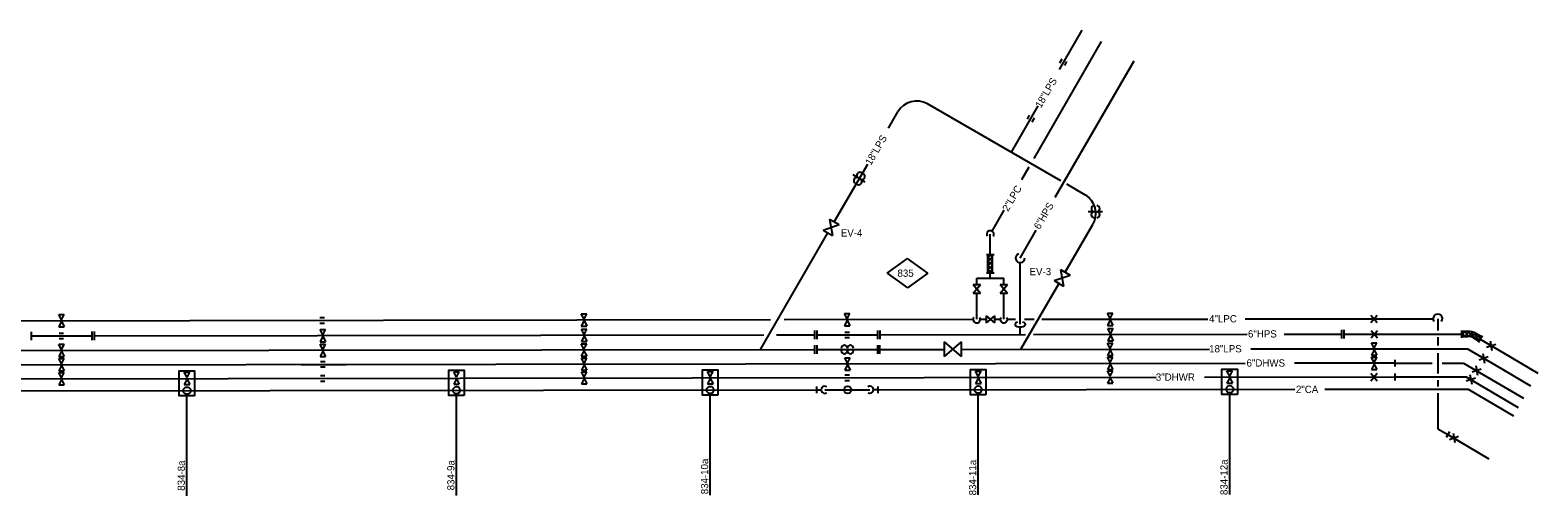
# Model space of a CAD drawing. Extents: x 9888 to 10178, y 10284 to 10314.
# Drawn here: x 10109 to 10178.2, y 10284.2 to 10305.6 of the extents above; entities that cross this region are included whole.
import ezdxf

# ---------------------------------------------------------------- set-up
doc = ezdxf.new("R2010")
doc.units = 0
for name, color, linetype in [('Level 51', 7, 'Continuous'), ('Level 52', 7, 'Continuous'), ('Level 53', 7, 'Continuous'), ('Level 54', 7, 'Continuous'), ('Level 55', 7, 'Continuous'), ('M-EQPM-N', 7, 'Continuous'), ('M-STEM-CONP', 7, 'Continuous'), ('M-STEM-CONP-N', 7, 'Continuous'), ('P-CMPA-PIPE', 7, 'Continuous'), ('P-CMPA-PIPE-N', 7, 'Continuous'), ('P-DOMW-HPIP', 7, 'Continuous'), ('P-DOMW-HPIP-N', 7, 'Continuous')]:
    doc.layers.add(name, color=color, linetype=linetype)

msp = doc.modelspace()

# ---------------------------------------------------------------- linework, layer by layer
at = {"layer": 'Level 51'}
for p, q in [((10155.104, 10299.749), (10158.206, 10305.122)), ((10154.54, 10298.773), (10154.881, 10299.363)), ((10153.174, 10296.406), (10153.727, 10297.365)), ((10153.092, 10295.333), (10153.092, 10296.264)), ((10148.356, 10294.475), (10149.289, 10295.148)), ((10150.222, 10294.475), (10149.289, 10295.148)), ((10152.92, 10295.333), (10153.263, 10295.333)), ((10152.994, 10295.213), (10152.968, 10295.239)), ((10152.968, 10295.188), (10152.994, 10295.213)), ((10152.994, 10295.025), (10152.968, 10295.051)), ((10152.968, 10294.999), (10152.994, 10295.025)), ((10152.994, 10295.213), (10153.091, 10295.311)), ((10152.994, 10295.025), (10153.195, 10295.227)), ((10153.195, 10295.012), (10152.994, 10295.213)), ((10152.994, 10295.025), (10153.088, 10294.931)), ((10153.088, 10294.931), (10152.994, 10294.836)), ((10153.195, 10295.2), (10153.085, 10295.311)), ((10153.088, 10294.931), (10153.195, 10295.038)), ((10153.195, 10294.823), (10153.088, 10294.931)), ((10148.356, 10294.475), (10149.289, 10293.803)), ((10150.222, 10294.475), (10149.289, 10293.803)), ((10152.469, 10293.952), (10152.469, 10294.248)), ((10152.469, 10294.248), (10153.714, 10294.248)), ((10152.92, 10294.499), (10153.263, 10294.499)), ((10152.994, 10294.836), (10152.968, 10294.862)), ((10152.968, 10294.811), (10152.994, 10294.836)), ((10152.994, 10294.648), (10152.968, 10294.674)), ((10152.968, 10294.622), (10152.994, 10294.648)), ((10152.994, 10294.648), (10153.195, 10294.85)), ((10153.195, 10294.634), (10152.994, 10294.836)), ((10153.124, 10294.518), (10152.994, 10294.648)), ((10153.052, 10294.518), (10153.195, 10294.661)), ((10153.092, 10294.248), (10153.092, 10294.499)), ((10153.714, 10293.952), (10153.714, 10294.248)), ((10152.302, 10293.952), (10152.636, 10293.952)), ((10152.302, 10293.564), (10152.636, 10293.952)), ((10152.302, 10293.952), (10152.636, 10293.564)), ((10152.302, 10293.564), (10152.636, 10293.564)), ((10152.469, 10292.355), (10152.469, 10293.564)), ((10153.547, 10293.952), (10153.881, 10293.952)), ((10153.547, 10293.564), (10153.881, 10293.952)), ((10153.547, 10293.952), (10153.881, 10293.564)), ((10153.547, 10293.564), (10153.881, 10293.564)), ((10153.714, 10292.355), (10153.714, 10293.564)), ((10073.354, 10292.244), (10142.991, 10292.341)), ((10110.434, 10292.333), (10110.31, 10292.581)), ((10110.31, 10292.581), (10110.558, 10292.581)), ((10110.434, 10292.264), (10110.31, 10292.016)), ((10110.434, 10292.333), (10110.558, 10292.581)), ((10110.434, 10292.264), (10110.558, 10292.016)), ((10122.307, 10292.436), (10122.511, 10292.436)), ((10122.307, 10292.186), (10122.511, 10292.186)), ((10134.434, 10292.365), (10134.31, 10292.612)), ((10134.31, 10292.612), (10134.558, 10292.612)), ((10134.434, 10292.295), (10134.31, 10292.047)), ((10134.434, 10292.365), (10134.558, 10292.612)), ((10134.434, 10292.295), (10134.558, 10292.047)), ((10143.628, 10292.342), (10152.304, 10292.355)), ((10146.518, 10292.38), (10146.394, 10292.628)), ((10146.394, 10292.628), (10146.641, 10292.628)), ((10146.518, 10292.311), (10146.394, 10292.063)), ((10146.518, 10292.38), (10146.641, 10292.628)), ((10146.518, 10292.311), (10146.641, 10292.063)), ((10152.633, 10292.356), (10152.883, 10292.356)), ((10152.913, 10292.189), (10152.913, 10292.523)), ((10153.301, 10292.189), (10152.913, 10292.523)), ((10152.913, 10292.189), (10153.301, 10292.523)), ((10153.301, 10292.189), (10153.301, 10292.523)), ((10153.301, 10292.356), (10153.55, 10292.356)), ((10153.879, 10292.357), (10154.246, 10292.357)), ((10154.658, 10292.357), (10155.112, 10292.358)), ((10155.461, 10292.359), (10163.09, 10292.368)), ((10158.601, 10292.396), (10158.477, 10292.644)), ((10158.477, 10292.644), (10158.725, 10292.644)), ((10158.601, 10292.326), (10158.477, 10292.079)), ((10158.601, 10292.396), (10158.725, 10292.644)), ((10158.601, 10292.326), (10158.725, 10292.079)), ((10164.799, 10292.371), (10173.411, 10292.382)), ((10170.572, 10292.212), (10170.864, 10292.552)), ((10170.572, 10292.552), (10170.864, 10292.212)), ((10173.644, 10292.382), (10173.644, 10291.845)), ((10110.31, 10292.016), (10110.558, 10292.016)), ((10134.31, 10292.047), (10134.558, 10292.047)), ((10134.441, 10291.66), (10134.317, 10291.907)), ((10134.317, 10291.907), (10134.565, 10291.907)), ((10134.441, 10291.59), (10134.317, 10291.342)), ((10134.441, 10291.66), (10134.565, 10291.907)), ((10134.441, 10291.59), (10134.565, 10291.342)), ((10143.272, 10291.637), (10145.018, 10291.64)), ((10145.025, 10291.835), (10145.025, 10291.444)), ((10145.128, 10291.835), (10145.128, 10291.444)), ((10145.128, 10291.64), (10147.924, 10291.644)), ((10146.394, 10292.063), (10146.641, 10292.063)), ((10146.416, 10291.768), (10146.62, 10291.768)), ((10146.416, 10291.518), (10146.62, 10291.518)), ((10147.924, 10291.448), (10147.924, 10291.839)), ((10148.027, 10291.448), (10148.027, 10291.839)), ((10154.466, 10291.652), (10154.466, 10292.007)), ((10158.477, 10292.079), (10158.725, 10292.079)), ((10158.608, 10291.691), (10158.484, 10291.939)), ((10158.484, 10291.939), (10158.732, 10291.939)), ((10158.608, 10291.622), (10158.484, 10291.374)), ((10158.608, 10291.691), (10158.732, 10291.939)), ((10158.608, 10291.622), (10158.732, 10291.374)), ((10166.585, 10291.668), (10169.227, 10291.671)), ((10169.227, 10291.866), (10169.227, 10291.475)), ((10169.33, 10291.866), (10169.33, 10291.475)), ((10169.33, 10291.671), (10172.125, 10291.674)), ((10169.553, 10291.671), (10174.73, 10291.676)), ((10170.585, 10291.502), (10170.877, 10291.842)), ((10170.585, 10291.842), (10170.877, 10291.502)), ((10173.644, 10291.539), (10173.644, 10291.151)), ((10174.754, 10291.645), (10174.884, 10291.775)), ((10174.754, 10291.716), (10174.897, 10291.573)), ((10174.858, 10291.801), (10174.884, 10291.775)), ((10174.871, 10291.573), (10175.072, 10291.775)), ((10174.884, 10291.775), (10174.91, 10291.801)), ((10174.884, 10291.775), (10175.086, 10291.573)), ((10175.047, 10291.801), (10175.193, 10291.547)), ((10175.059, 10291.573), (10175.248, 10291.762)), ((10175.072, 10291.775), (10175.098, 10291.801)), ((10175.407, 10291.693), (10175.166, 10291.555)), ((10175.209, 10291.779), (10175.282, 10291.503)), ((10175.259, 10291.516), (10175.535, 10291.589)), ((10175.363, 10291.719), (10175.372, 10291.684)), ((10175.372, 10291.684), (10175.445, 10291.408)), ((10175.526, 10291.625), (10175.535, 10291.589)), ((10175.535, 10291.589), (10175.57, 10291.599)), ((10175.535, 10291.589), (10175.57, 10291.456)), ((10134.317, 10291.342), (10134.565, 10291.342)), ((10158.484, 10291.374), (10158.732, 10291.374)), ((10173.644, 10290.804), (10173.644, 10289.865)), ((10175.422, 10291.421), (10175.573, 10291.462)), ((10173.644, 10289.558), (10173.644, 10289.273)), ((10173.644, 10288.966), (10173.644, 10287.329)), ((10173.644, 10287.329), (10174.11, 10287.056)), ((10174.189, 10287.191), (10174.03, 10286.921))]:
    msp.add_line(p, q, dxfattribs=at)
msp.add_lwpolyline([(10153.195, 10295.311), (10152.968, 10295.311), (10152.968, 10294.518), (10153.195, 10294.518)], close=True, dxfattribs=at)
for centre, radius, start, end in [((10153.092, 10296.264), 0.164, 326.0383, 213.83623), ((10152.469, 10292.355), 0.164, 146.0383, 33.83623), ((10153.714, 10292.355), 0.164, 146.0383, 33.83623), ((10173.644, 10292.382), 0.214, 326.0383, 213.83623)]:
    msp.add_arc(centre, radius, start, end, dxfattribs=at)
at = {"layer": 'Level 52'}
for p, q in [((10174.11, 10287.056), (10175.992, 10285.951)), ((10174.175, 10286.836), (10174.599, 10286.98)), ((10174.347, 10287.128), (10174.426, 10286.688))]:
    msp.add_line(p, q, dxfattribs=at)
at = {"layer": 'Level 53'}
for p, q in [((10175.592, 10291.443), (10176.66, 10290.816)), ((10175.881, 10291.076), (10176.305, 10291.221)), ((10176.054, 10291.369), (10176.132, 10290.928)), ((10176.66, 10290.816), (10178.239, 10289.888))]:
    msp.add_line(p, q, dxfattribs=at)
at = {"layer": 'Level 54'}
for p, q in [((10174.735, 10291.849), (10174.735, 10291.505)), ((10174.754, 10291.801), (10174.754, 10291.573)), ((10175.02, 10291.801), (10174.754, 10291.801)), ((10174.754, 10291.573), (10175.026, 10291.573)), ((10175.243, 10291.65), (10175.241, 10291.658)), ((10175.277, 10291.505), (10175.518, 10291.366)), ((10175.632, 10291.563), (10175.397, 10291.699)), ((10175.675, 10291.594), (10175.502, 10291.296)), ((10175.518, 10291.366), (10175.632, 10291.563))]:
    msp.add_line(p, q, dxfattribs=at)
for centre, radius, start in [((10175.02, 10291.051), 0.75, 59.85951), ((10175.026, 10291.073), 0.5, 59.8589)]:
    msp.add_arc(centre, radius, start, 90, dxfattribs=at)
at = {"layer": 'Level 55'}
for p, q in [((10171.669, 10289.707), (10174.94, 10289.711)), ((10174.94, 10289.711), (10177.33, 10288.307)), ((10174.95, 10289.523), (10175.374, 10289.668)), ((10175.123, 10289.816), (10175.201, 10289.375))]:
    msp.add_line(p, q, dxfattribs=at)
at = {"layer": 'M-EQPM-N'}
for p, q in [((10116.199, 10284.243), (10116.199, 10288.84)), ((10128.58, 10284.26), (10128.58, 10288.857)), ((10140.233, 10284.275), (10140.233, 10288.872)), ((10152.541, 10284.291), (10152.541, 10288.889)), ((10164.086, 10284.307), (10164.086, 10288.904))]:
    msp.add_line(p, q, dxfattribs=at)
for points in [[(10116.552, 10288.84), (10115.847, 10288.84), (10115.847, 10289.995), (10116.552, 10289.995)], [(10128.933, 10288.857), (10128.228, 10288.857), (10128.228, 10290.012), (10128.933, 10290.012)], [(10140.586, 10288.872), (10139.881, 10288.872), (10139.881, 10290.027), (10140.586, 10290.027)], [(10152.893, 10288.889), (10152.188, 10288.889), (10152.188, 10290.043), (10152.893, 10290.043)], [(10164.438, 10288.904), (10163.733, 10288.904), (10163.733, 10290.059), (10164.438, 10290.059)]]:
    msp.add_lwpolyline(points, close=True, dxfattribs=at)
at = {"layer": 'M-STEM-CONP'}
for p, q in [((10156.264, 10303.841), (10157.305, 10305.644)), ((10156.077, 10297.962), (10159.702, 10304.24)), ((10156.292, 10304.148), (10156.394, 10304.325)), ((10156.509, 10304.023), (10156.611, 10304.2)), ((10148.415, 10301.14), (10148.846, 10301.887)), ((10156.332, 10298.72), (10150.213, 10302.253)), ((10154.064, 10300.03), (10155.293, 10302.159)), ((10154.797, 10301.556), (10154.9, 10301.733)), ((10155.014, 10301.431), (10155.116, 10301.608)), ((10145.929, 10296.835), (10147.462, 10299.489)), ((10146.995, 10298.871), (10146.789, 10298.99)), ((10147.124, 10298.797), (10147.124, 10298.797)), ((10147.353, 10298.664), (10147.152, 10298.78)), ((10157.44, 10298.08), (10156.608, 10298.561)), ((10157.83, 10297.299), (10157.592, 10297.299)), ((10157.979, 10297.3), (10157.978, 10297.3)), ((10158.243, 10297.299), (10158.011, 10297.299)), ((10142.536, 10290.962), (10145.636, 10296.331)), ((10145.42, 10296.457), (10146.146, 10296.709)), ((10145.42, 10296.457), (10145.852, 10296.205)), ((10145.713, 10296.961), (10146.146, 10296.709)), ((10145.713, 10296.961), (10145.852, 10296.205)), ((10154.466, 10295.171), (10155.205, 10296.451)), ((10156.537, 10294.516), (10157.806, 10296.714)), ((10154.466, 10292.127), (10154.466, 10294.957)), ((10156.029, 10294.137), (10156.755, 10294.388)), ((10156.323, 10294.641), (10156.755, 10294.388)), ((10156.323, 10294.641), (10156.462, 10293.885)), ((10154.495, 10290.978), (10156.234, 10293.99)), ((10156.029, 10294.137), (10156.462, 10293.885)), ((10109.049, 10291.788), (10109.049, 10291.397)), ((10109.049, 10291.592), (10111.844, 10291.596)), ((10110.332, 10291.721), (10110.536, 10291.721)), ((10110.332, 10291.471), (10110.536, 10291.471)), ((10111.844, 10291.4), (10111.844, 10291.791)), ((10111.948, 10291.4), (10111.948, 10291.791)), ((10111.948, 10291.596), (10142.691, 10291.637)), ((10122.441, 10291.644), (10122.317, 10291.892)), ((10122.317, 10291.892), (10122.565, 10291.892)), ((10122.441, 10291.575), (10122.317, 10291.327)), ((10122.441, 10291.644), (10122.565, 10291.892)), ((10122.441, 10291.575), (10122.565, 10291.327)), ((10148.027, 10291.644), (10154.711, 10291.653)), ((10155.07, 10291.653), (10164.895, 10291.666)), ((10085.43, 10290.887), (10145.023, 10290.966)), ((10110.432, 10290.961), (10110.309, 10291.209)), ((10110.309, 10291.209), (10110.556, 10291.209)), ((10110.432, 10290.892), (10110.309, 10290.644)), ((10110.432, 10290.961), (10110.556, 10291.209)), ((10110.432, 10290.892), (10110.556, 10290.644)), ((10122.432, 10290.961), (10122.309, 10291.209)), ((10122.309, 10291.209), (10122.556, 10291.209)), ((10122.432, 10290.892), (10122.309, 10290.644)), ((10122.317, 10291.327), (10122.565, 10291.327)), ((10122.432, 10290.961), (10122.556, 10291.209)), ((10122.432, 10290.892), (10122.556, 10290.644)), ((10148.03, 10290.97), (10150.976, 10290.974)), ((10151.753, 10290.975), (10163.153, 10290.99)), ((10165.058, 10290.992), (10175.014, 10291.003)), ((10170.724, 10291.024), (10170.6, 10291.272)), ((10170.6, 10291.272), (10170.848, 10291.272)), ((10170.724, 10290.954), (10170.6, 10290.707)), ((10170.724, 10291.024), (10170.848, 10291.272)), ((10170.724, 10290.954), (10170.848, 10290.707)), ((10175.014, 10291.003), (10176.319, 10290.236)), ((10175.712, 10290.789), (10175.79, 10290.348)), ((10110.309, 10290.644), (10110.556, 10290.644)), ((10122.309, 10290.644), (10122.556, 10290.644)), ((10170.6, 10290.707), (10170.848, 10290.707)), ((10175.539, 10290.496), (10175.963, 10290.64)), ((10176.319, 10290.236), (10177.903, 10289.306))]:
    msp.add_line(p, q, dxfattribs=at)
for centre, radius, start, end in [((10149.712, 10301.387), 1, 59.99985, 149.99956), ((10147.102, 10298.971), 0.14, 60, 240), ((10146.962, 10298.729), 0.14, 60, 240), ((10147.054, 10298.676), 0.14, 240, 60), ((10147.194, 10298.918), 0.14, 240, 60), ((10156.94, 10297.214), 1, 329.99958, 59.99986), ((10157.872, 10297.16), 0.14, 90, 270), ((10157.873, 10297.44), 0.14, 90, 270), ((10157.978, 10297.44), 0.14, 270, 90), ((10157.979, 10297.16), 0.14, 270, 90), ((10154.466, 10295.171), 0.214, 113.08412, 0.88206)]:
    msp.add_arc(centre, radius, start, end, dxfattribs=at)
msp.add_ellipse((10154.466, 10292.127), major_axis=(-0.239, 0), ratio=0.503291, start_param=5.263815, end_param=10.432096, dxfattribs=at)
at = {"layer": 'M-STEM-CONP-N'}
for p, q in [((10134.432, 10290.977), (10134.309, 10291.225)), ((10134.309, 10291.225), (10134.556, 10291.225)), ((10134.432, 10290.907), (10134.309, 10290.66)), ((10134.432, 10290.977), (10134.556, 10291.225)), ((10134.432, 10290.907), (10134.556, 10290.66)), ((10145.023, 10291.161), (10145.023, 10290.77)), ((10145.127, 10291.161), (10145.127, 10290.77)), ((10145.127, 10290.966), (10147.922, 10290.97)), ((10147.922, 10290.774), (10147.922, 10291.165)), ((10148.025, 10290.774), (10148.025, 10291.165)), ((10150.976, 10291.316), (10150.976, 10290.648)), ((10150.976, 10291.316), (10151.753, 10290.648)), ((10151.753, 10291.316), (10150.976, 10290.648)), ((10151.753, 10291.316), (10151.753, 10290.648)), ((10158.599, 10291.008), (10158.475, 10291.256)), ((10158.475, 10291.256), (10158.723, 10291.256)), ((10158.599, 10290.939), (10158.475, 10290.691)), ((10158.599, 10291.008), (10158.723, 10291.256)), ((10158.599, 10290.939), (10158.723, 10290.691)), ((10134.309, 10290.66), (10134.556, 10290.66)), ((10158.475, 10290.691), (10158.723, 10290.691))]:
    msp.add_line(p, q, dxfattribs=at)
for centre, start, end in [((10146.39, 10291.022), 0, 180), ((10146.39, 10290.917), 180, 0), ((10146.67, 10291.023), 0, 180), ((10146.67, 10290.916), 180, 0)]:
    msp.add_arc(centre, 0.14, start, end, dxfattribs=at)
at = {"layer": 'P-CMPA-PIPE'}
for p, q in [((10085.43, 10289.037), (10145.135, 10289.116)), ((10147.925, 10289.12), (10167.072, 10289.145)), ((10168.456, 10289.146), (10175.033, 10289.153)), ((10175.033, 10289.153), (10177.119, 10287.928))]:
    msp.add_line(p, q, dxfattribs=at)
at = {"layer": 'P-CMPA-PIPE-N'}
for p, q in [((10145.127, 10288.959), (10145.127, 10289.273)), ((10145.127, 10289.116), (10145.322, 10289.116)), ((10145.487, 10289.116), (10147.561, 10289.119)), ((10147.922, 10289.12), (10147.726, 10289.119)), ((10147.922, 10289.276), (10147.922, 10288.963))]:
    msp.add_line(p, q, dxfattribs=at)
for centre in [(10116.2, 10289.078), (10128.581, 10289.094), (10140.234, 10289.109), (10146.544, 10289.114), (10152.542, 10289.126), (10164.087, 10289.141)]:
    msp.add_circle(centre, 0.167, dxfattribs=at)
for centre, start, end in [((10145.487, 10289.116), 56.0383, 303.83623), ((10147.561, 10289.119), 236.0383, 123.83623)]:
    msp.add_arc(centre, 0.164, start, end, dxfattribs=at)
at = {"layer": 'P-DOMW-HPIP'}
for p, q in [((10171.669, 10290.344), (10173.391, 10290.346)), ((10173.838, 10290.346), (10174.831, 10290.347)), ((10174.831, 10290.347), (10177.58, 10288.733)), ((10175.217, 10289.937), (10175.641, 10290.082)), ((10175.39, 10290.23), (10175.468, 10289.789))]:
    msp.add_line(p, q, dxfattribs=at)
at = {"layer": 'P-DOMW-HPIP-N'}
for p, q in [((10075.709, 10290.221), (10164.791, 10290.337)), ((10110.434, 10290.305), (10110.31, 10290.553)), ((10110.31, 10290.553), (10110.558, 10290.553)), ((10110.434, 10290.236), (10110.31, 10289.988)), ((10110.434, 10290.305), (10110.558, 10290.553)), ((10110.434, 10290.236), (10110.558, 10289.988)), ((10121.443, 10290.28), (10123.504, 10290.282)), ((10122.336, 10290.421), (10122.54, 10290.421)), ((10122.336, 10290.171), (10122.54, 10290.171)), ((10134.442, 10290.33), (10134.318, 10290.578)), ((10134.318, 10290.578), (10134.565, 10290.578)), ((10134.442, 10290.26), (10134.318, 10290.013)), ((10134.442, 10290.33), (10134.565, 10290.578)), ((10134.442, 10290.26), (10134.565, 10290.013)), ((10146.531, 10290.343), (10146.407, 10290.591)), ((10146.407, 10290.591), (10146.655, 10290.591)), ((10146.531, 10290.274), (10146.407, 10290.026)), ((10146.531, 10290.343), (10146.655, 10290.591)), ((10146.531, 10290.274), (10146.655, 10290.026)), ((10158.601, 10290.366), (10158.477, 10290.613)), ((10158.477, 10290.613), (10158.725, 10290.613)), ((10158.601, 10290.296), (10158.477, 10290.048)), ((10158.601, 10290.366), (10158.725, 10290.613)), ((10158.601, 10290.296), (10158.725, 10290.048)), ((10171.669, 10290.344), (10167.067, 10290.344)), ((10170.726, 10290.363), (10170.602, 10290.61)), ((10170.602, 10290.61), (10170.85, 10290.61)), ((10170.726, 10290.293), (10170.602, 10290.045)), ((10170.726, 10290.363), (10170.85, 10290.61)), ((10170.726, 10290.293), (10170.85, 10290.045)), ((10171.669, 10290.501), (10171.669, 10290.188)), ((10073.838, 10289.582), (10160.703, 10289.695)), ((10110.31, 10289.988), (10110.558, 10289.988)), ((10110.434, 10289.665), (10110.31, 10289.913)), ((10110.31, 10289.913), (10110.558, 10289.913)), ((10110.434, 10289.595), (10110.31, 10289.348)), ((10110.434, 10289.665), (10110.558, 10289.913)), ((10110.434, 10289.595), (10110.558, 10289.348)), ((10116.201, 10289.675), (10116.077, 10289.923)), ((10116.077, 10289.923), (10116.325, 10289.923)), ((10116.201, 10289.605), (10116.077, 10289.358)), ((10116.201, 10289.675), (10116.325, 10289.923)), ((10116.201, 10289.605), (10116.325, 10289.358)), ((10122.333, 10289.768), (10122.537, 10289.768)), ((10122.333, 10289.518), (10122.537, 10289.518)), ((10128.582, 10289.691), (10128.458, 10289.939)), ((10128.458, 10289.939), (10128.706, 10289.939)), ((10128.582, 10289.622), (10128.458, 10289.374)), ((10128.582, 10289.691), (10128.706, 10289.939)), ((10128.582, 10289.622), (10128.706, 10289.374)), ((10134.318, 10290.013), (10134.565, 10290.013)), ((10134.442, 10289.701), (10134.318, 10289.949)), ((10134.318, 10289.949), (10134.565, 10289.949)), ((10134.442, 10289.632), (10134.318, 10289.384)), ((10134.442, 10289.701), (10134.565, 10289.949)), ((10134.442, 10289.632), (10134.565, 10289.384)), ((10140.234, 10289.707), (10140.111, 10289.954)), ((10140.111, 10289.954), (10140.358, 10289.954)), ((10140.234, 10289.637), (10140.111, 10289.389)), ((10140.111, 10289.389), (10140.358, 10289.389)), ((10140.234, 10289.707), (10140.358, 10289.954)), ((10140.234, 10289.637), (10140.358, 10289.389)), ((10146.407, 10290.026), (10146.655, 10290.026)), ((10146.416, 10289.8), (10146.62, 10289.8)), ((10146.416, 10289.55), (10146.62, 10289.55)), ((10152.542, 10289.723), (10152.418, 10289.971)), ((10152.418, 10289.971), (10152.666, 10289.971)), ((10152.542, 10289.654), (10152.418, 10289.406)), ((10152.418, 10289.406), (10152.666, 10289.406)), ((10152.542, 10289.723), (10152.666, 10289.971)), ((10152.542, 10289.654), (10152.666, 10289.406)), ((10158.477, 10290.048), (10158.725, 10290.048)), ((10158.601, 10289.737), (10158.477, 10289.985)), ((10158.477, 10289.985), (10158.725, 10289.985)), ((10158.601, 10289.667), (10158.477, 10289.42)), ((10158.477, 10289.42), (10158.725, 10289.42)), ((10158.601, 10289.737), (10158.725, 10289.985)), ((10158.601, 10289.667), (10158.725, 10289.42)), ((10162.937, 10289.698), (10171.669, 10289.707)), ((10164.087, 10289.738), (10163.963, 10289.986)), ((10163.963, 10289.986), (10164.211, 10289.986)), ((10164.087, 10289.669), (10163.963, 10289.421)), ((10163.963, 10289.421), (10164.211, 10289.421)), ((10164.087, 10289.738), (10164.211, 10289.986)), ((10164.087, 10289.669), (10164.211, 10289.421)), ((10170.568, 10289.535), (10170.859, 10289.875)), ((10170.568, 10289.875), (10170.859, 10289.535)), ((10170.602, 10290.045), (10170.85, 10290.045)), ((10171.669, 10289.864), (10171.669, 10289.55)), ((10110.31, 10289.348), (10110.558, 10289.348)), ((10116.077, 10289.358), (10116.325, 10289.358)), ((10128.458, 10289.374), (10128.706, 10289.374)), ((10134.318, 10289.384), (10134.565, 10289.384))]:
    msp.add_line(p, q, dxfattribs=at)

# ---------------------------------------------------------------- texts
at = {"layer": 'Level 51'}
msp.add_text('2"LPC', height=0.3333, rotation=59.6379, dxfattribs=at).set_placement((10153.91, 10297.285))
for s, p in [('835', (10148.83, 10294.309)), ('4"LPC', (10163.142, 10292.215)), ('6"HPS', (10164.926, 10291.521))]:
    msp.add_text(s, height=0.3333, dxfattribs=at).set_placement(p)
at = {"layer": 'M-EQPM-N'}
for s, p in [('834-10a', (10140.137, 10284.317)), ('834-8a', (10116.103, 10284.48)), ('834-9a', (10128.484, 10284.496)), ('834-11a', (10152.445, 10284.265)), ('834-12a', (10163.99, 10284.281))]:
    msp.add_text(s, height=0.3333, rotation=90, dxfattribs=at).set_placement(p)
at = {"layer": 'M-STEM-CONP'}
for s, p in [('18"LPS', (10155.417, 10302.039)), ('18"LPS', (10147.607, 10299.406)), ('6"HPS', (10155.354, 10296.457))]:
    msp.add_text(s, height=0.3333, rotation=59.6379, dxfattribs=at).set_placement(p)
for s, p in [('EV-4', (10146.227, 10296.16)), ('EV-3', (10154.896, 10294.384)), ('18"LPS', (10163.145, 10290.836))]:
    msp.add_text(s, height=0.3333, dxfattribs=at).set_placement(p)
at = {"layer": 'P-CMPA-PIPE'}
msp.add_text('2"CA', height=0.3333, dxfattribs=at).set_placement((10167.129, 10288.971))
at = {"layer": 'P-DOMW-HPIP'}
msp.add_text('6"DHWS', height=0.3333, dxfattribs=at).set_placement((10164.861, 10290.183))
at = {"layer": 'P-DOMW-HPIP-N'}
msp.add_text('3"DHWR', height=0.3333, dxfattribs=at).set_placement((10160.695, 10289.535))

doc.saveas('drawing.dxf')
